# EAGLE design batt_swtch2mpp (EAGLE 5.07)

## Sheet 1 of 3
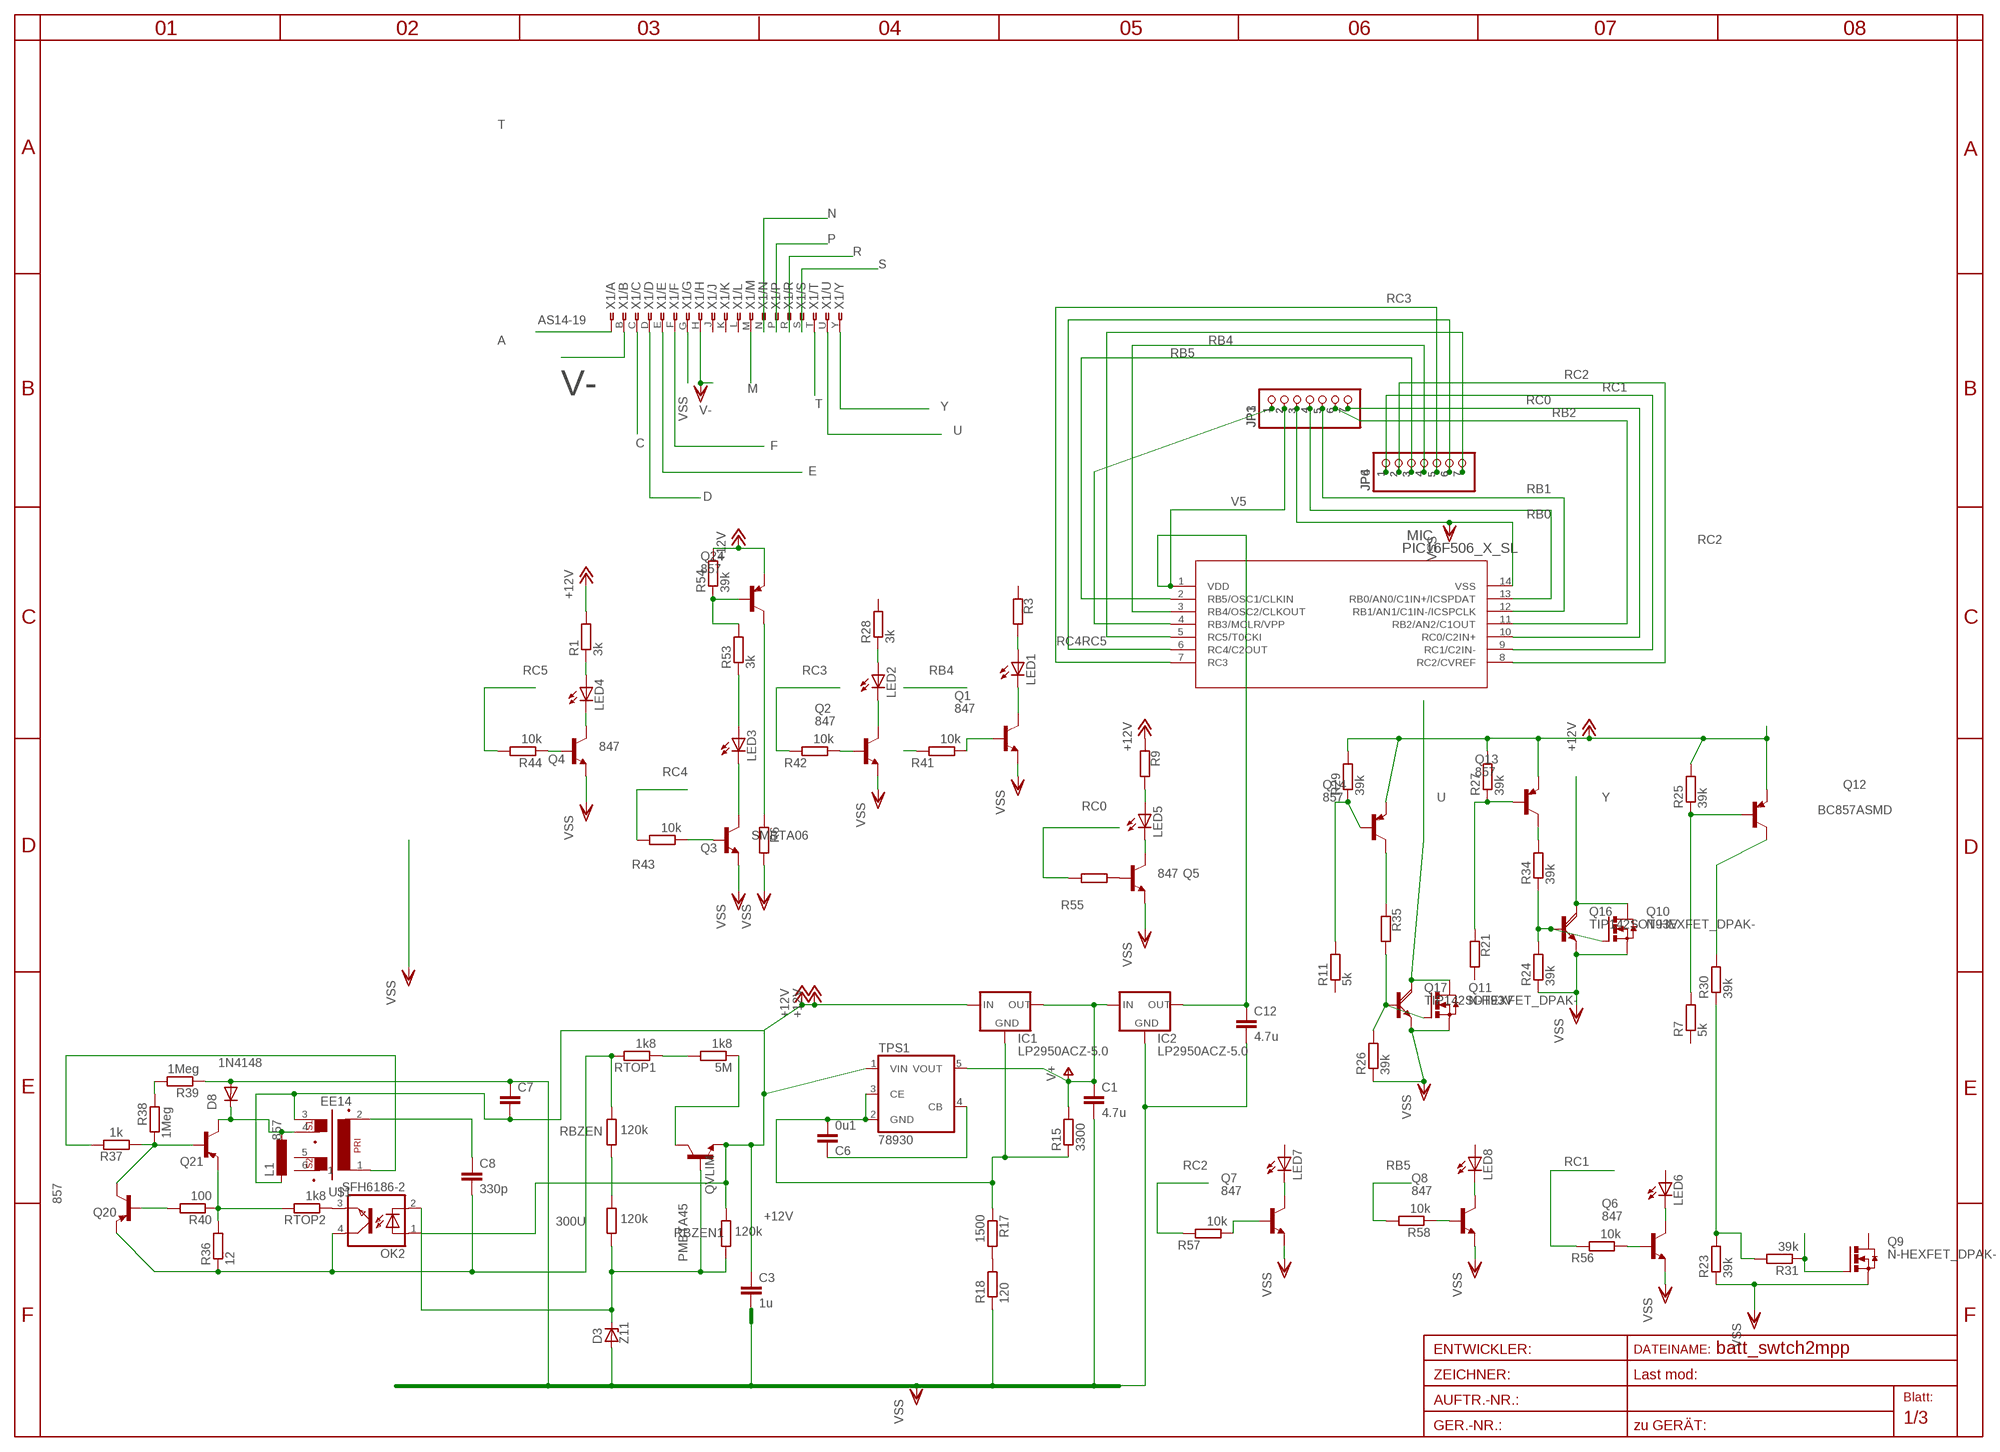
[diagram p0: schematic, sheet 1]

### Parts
5M  1k8  R-EU_R1206  [R1206]
300U  120k  R-EU_R1206  [R1206]
C1  4.7u  C-EUC1206  [C1206]
C3  1u  C-EUC1206  [C1206]
C6  0u1  C-EUC0805  [C0805]
C7  C-EU025-025X050  [C025-025X050]
C8  330p  C-EUC0805  [C0805]
C12  4.7u  C-EUC1206  [C1206]
D3  Z11  ZENER-DIODESOD80C  [SOD80C]
D8  1N4148  DIODE-SMA-DO214  [SMA-DO214AC]
IC1  LP2950ACZ-5.0  [TO92]
IC2  LP2950ACZ-5.0  [TO92]
JP1  PINHD-1X7  [1X07]
JP3  PINHD-1X7  [1X07]
JP4  PINHD-1X7  [1X07]
JP6  PINHD-1X7  [1X07]
L1  L-EU0204/5  [0204/5]
LED1  LEDCHIPLED_1206  [CHIPLED_1206]
LED2  LEDCHIPLED_1206  [CHIPLED_1206]
LED3  LEDCHIPLED_1206  [CHIPLED_1206]
LED4  LEDCHIPLED_1206  [CHIPLED_1206]
LED5  LEDCHIPLED_1206  [CHIPLED_1206]
LED6  LEDCHIPLED_1206  [CHIPLED_1206]
LED7  LEDCHIPLED_1206  [CHIPLED_1206]
LED8  LEDCHIPLED_1206  [CHIPLED_1206]
MIC  PIC16F506_X_SL  [SOIC14_N_MC]
OK2  SFH6186-2  [SMD4]
Q1  847  BC847ASMD  [SOT23]
Q2  847  BC847ASMD  [SOT23]
Q3  SMBTA06  BC847ASMD  [SOT23]
Q4  847  BC847ASMD  [SOT23]
Q5  847  BC847ASMD  [SOT23]
Q6  847  BC847ASMD  [SOT23]
Q7  847  BC847ASMD  [SOT23]
Q8  847  BC847ASMD  [SOT23]
Q9  N-HEXFET_DPAK-  [TO252]
Q10  N-HEXFET_DPAK-  [TO252]
Q11  N-HEXFET_DPAK-  [TO252]
Q12  BC857ASMD  [SOT23-BEC]
Q13  857  BC857ASMD  [SOT23-BEC]
Q14  857  BC857ASMD  [SOT23-BEC]
Q16  TIP142SOT93V  [SOT93V]
Q17  TIP142SOT93V  [SOT93V]
Q20  857  BC857ASMD  [SOT23-BEC]
Q21  857  BC857ASMD  [SOT23-BEC]
Q24  857  BC857ASMD  [SOT23-BEC]
QVLIM  PMBTA45  BC847ALT1SMD  [SOT23]
R1  3k  R-EU_R0805  [R0805]
R3  39k  R-EU_R0805  [R0805]
R6  39k  R-EU_R0805  [R0805]
R7  5k  R-EU_R0805  [R0805]
R9  5k  R-EU_R0805  [R0805]
R11  5k  R-EU_R0805  [R0805]
R15  3300  R-EU_R0805  [R0805]
R17  1500  R-EU_R0805  [R0805]
R18  120  R-EU_R0805  [R0805]
R21  5k  R-EU_R0805  [R0805]
R23  39k  R-EU_R0805  [R0805]
R24  39k  R-EU_R0805  [R0805]
R25  39k  R-EU_R0805  [R0805]
R26  39k  R-EU_R0805  [R0805]
R27  39k  R-EU_R0805  [R0805]
R28  3k  R-EU_R0805  [R0805]
R29  39k  R-EU_R0805  [R0805]
R30  39k  R-EU_R0805  [R0805]
R31  39k  R-EU_R0805  [R0805]
R34  39k  R-EU_R0805  [R0805]
R35  39k  R-EU_R0805  [R0805]
R36  12  R-EU_R0805  [R0805]
R37  1k  R-EU_R0805  [R0805]
R38  1Meg  R-EU_R1206  [R1206]
R39  1Meg  R-EU_R1206  [R1206]
R40  100  R-EU_R0805  [R0805]
R41  10k  R-EU_R0805  [R0805]
R42  10k  R-EU_R0805  [R0805]
R43  10k  R-EU_R0805  [R0805]
R44  10k  R-EU_R0805  [R0805]
R53  3k  R-EU_R0805  [R0805]
R54  39k  R-EU_R0805  [R0805]
R55  10k  R-EU_R0805  [R0805]
R56  10k  R-EU_R0805  [R0805]
R57  10k  R-EU_R0805  [R0805]
R58  10k  R-EU_R0805  [R0805]
RBZEN  120k  R-EU_R1206  [R1206]
RBZEN1  120k  R-EU_R0805  [R0805]
RTOP1  1k8  R-EU_R1206  [R1206]
RTOP2  1k8  R-EU_R1206  [R1206]
TPS1  78930  TPS78930SOT23-5  [SOT25]
U$1  EE14  [EE14]
X1  AS14-19  AS14-19OLIVE  [Y28M-19TK]

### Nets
+12V: C3.1 C7.2 IC1.3(IN) L1.2 OK2.1(A) Q12.E Q13.E Q14.E Q24.E QVLIM.2(E) R1.2 R9.2 R25.2 R27.2 R29.2 R54.2 RBZEN1.1 TPS1.1(VIN) U$1.3
A: X1.A ; also sheet 2,3
B1C2: Q20.C Q21.B R37.1 R38.1
BOOST_EN: Q24.C R6.2 ; also sheet 3
C: X1.C ; also sheet 3
C1: D8.K(C) L1.1 Q21.C U$1.4
CB: 300U.2 D3.C OK2.2(C) QVLIM.1(B) RBZEN1.2
D: X1.D
E: X1.E
EB: Q21.E R36.2 R40.1 RTOP2.2
F: X1.F
G: C8.2 OK2.4(COL) Q20.E R36.1 RBZEN.1 RTOP1.2 X1.G ; also sheet 2,3
GND1: C6.1 TPS1.4(CB)
M: X1.M
N: X1.N
N$1: 300U.1 RBZEN.2
N$3: OK2.3(EMIT) RTOP2.1
N$4: Q8.1(B) R58.1
N$6: Q3.1(B) R43.1
N$7: LED6.C Q6.3(C)
N$8: R17.2 R18.2
N$9: R41.2
N$10: LED8.C Q8.3(C)
N$11: Q2.1(B) R42.1
N$12: Q1.1(B) R41.1
N$14: Q5.1(B) R55.1
N$16: 5M.1 QVLIM.3(C)
N$17: LED7.C Q7.3(C)
N$19: LED1.C Q1.3(C)
N$20: LED1.A R3.1
N$21: Q14.B R11.2 R29.1
N$22: LED2.C Q2.3(C)
N$25: LED2.A R28.1
N$28: Q6.1(B) R56.1
N$29: 5M.2 RTOP1.1
N$30: Q4.1(B) R44.1
N$31: Q7.1(B) R57.1
N$32: LED3.C Q3.3(C)
N$33: LED4.C Q4.3(C)
N$36: LED4.A R1.1
N$37: Q12.C R30.2
N$47: LED5.A R9.1
N$49: Q14.C R35.2
N$50: R23.2 R30.1 R31.2
N$51: Q10.1(G) Q16.B R24.2 R34.1
N$52: LED5.C Q5.3(C)
N$53: Q12.B R7.2 R25.1
N$54: Q9.1(G) R31.1
N$55: Q13.B R21.2 R27.1
N$57: Q13.C R34.2
N$59: Q11.1(G) Q17.B R26.2 R35.1
N$60: R37.2 U$1.1
N$61: C8.1 U$1.2
N$62: R38.2 R39.2
N$63: Q20.B R40.2
N$81: Q24.B R53.2 R54.1
N$82: LED3.A R53.1
P: X1.P
R: X1.R
RB0: JP1.4 JP3.4 MIC.13(RB0/AN0/C1IN+/ICSPDAT) ; also sheet 2
RB1: JP1.5 JP3.5 MIC.12(RB1/AN1/C1IN-/ICSPCLK) ; also sheet 2
RB2: JP1.6 JP3.6 MIC.11(RB2/AN2/C1OUT) ; also sheet 2
RB4: JP4.4 JP6.4 MIC.3(RB4/OSC2/CLKOUT)
RB5: JP4.3 JP6.3 MIC.2(RB5/OSC1/CLKIN) R58.2
RC0: JP1.7 JP3.7 MIC.10(RC0/C2IN+) R55.2
RC1: JP4.1 JP6.1 MIC.9(RC1/C2IN-) R56.2
RC2: JP4.2 JP6.2 MIC.8(RC2/CVREF) R57.2
RC3: JP4.5 JP6.5 MIC.7(RC3) R42.2
RC4: JP4.6 JP6.6 MIC.6(RC4/C2OUT) R43.2
RC5: JP4.7 JP6.7 MIC.5(RC5/T0CKI) R44.2
S: X1.S ; also sheet 2
T: X1.T ; also sheet 2
U: Q11.3(D) Q17.C X1.U
V5: C12.1 IC2.1(OUT) JP1.2 JP3.2 MIC.1(VDD) ; also sheet 2
V+: C1.1 IC1.1(OUT) IC2.3(IN) R15.2 TPS1.5(VOUT) ; also sheet 3
V-: C1.2 C3.2 C6.2 C7.1 C12.2 D3.A D8.A IC1.2(GND) IC2.2(GND) JP1.3 JP3.3 MIC.14(VSS) Q1.2(E) Q2.2(E) Q3.2(E) Q4.2(E) Q5.2(E) Q6.2(E) Q7.2(E) Q8.2(E) Q9.2(S) Q10.2(S) Q11.2(S) Q16.E Q17.E R6.1 R15.1 R17.1 R18.1 R23.1 R24.1 R26.1 R39.1 TPS1.2(GND) TPS1.3(CE) X1.B X1.H ; supply symbol labelled VSS ; also sheet 2,3
WIND: JP1.1 JP3.1 MIC.4(RB3/MCLR/VPP)
Y: Q10.3(D) Q16.C X1.Y
Unconnected: LED6.A LED7.A LED8.A Q9.3(D) R3.2 R7.1 R11.1 R21.1 R28.2 U$1.5 U$1.6 X1.J X1.K X1.L

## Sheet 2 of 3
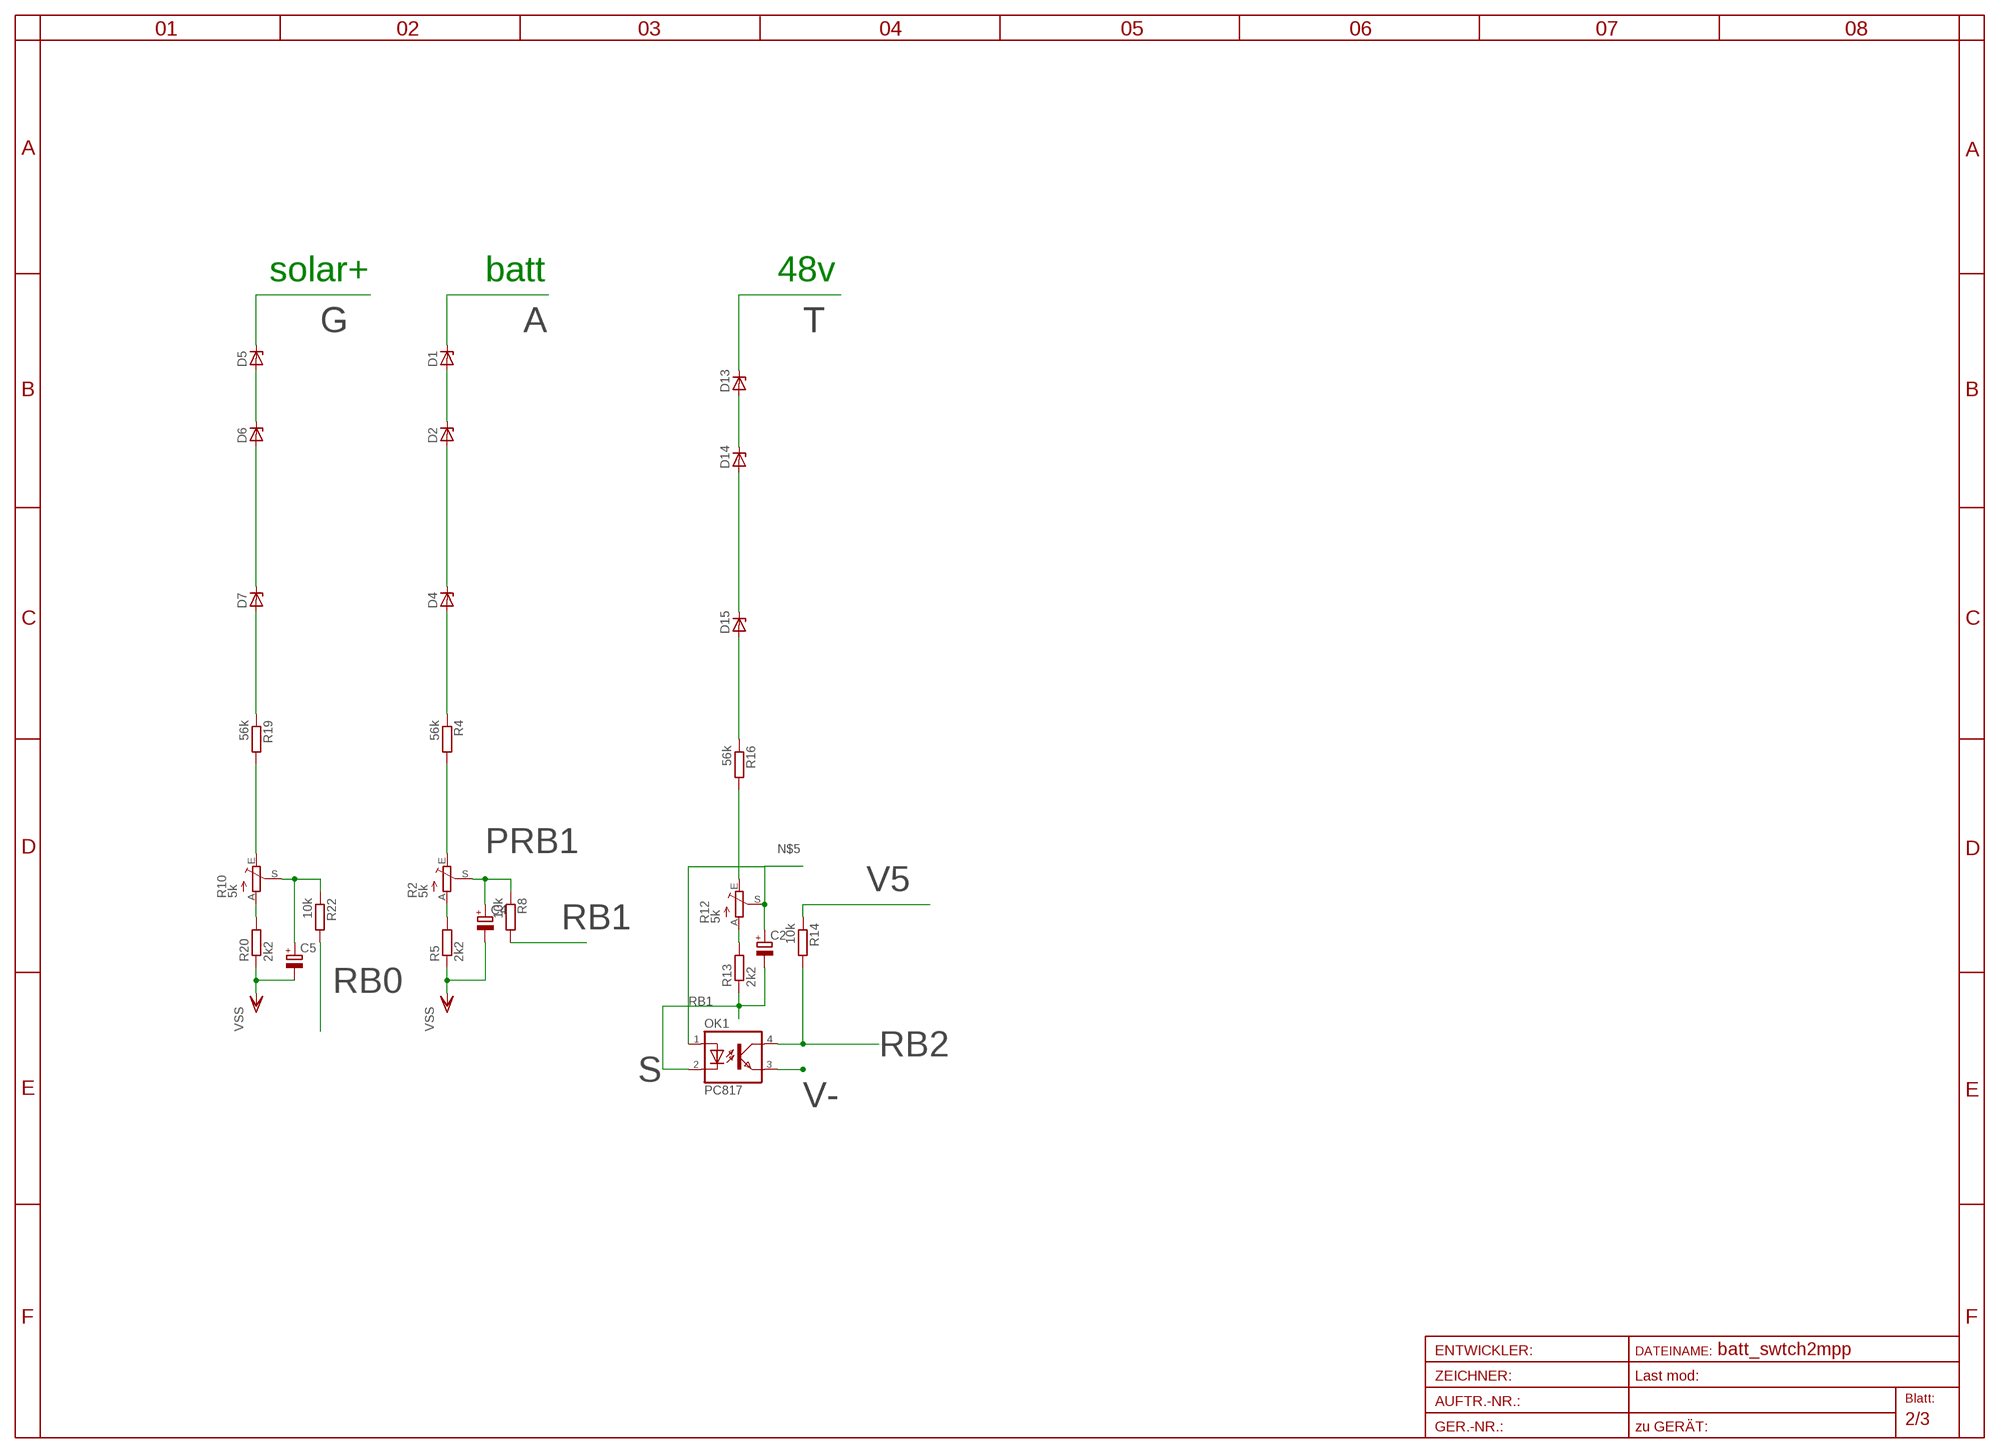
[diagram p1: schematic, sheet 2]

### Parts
C2  CPOL-EUE2,5-6E  [E2,5-6E]
C4  CPOL-EUE2,5-6E  [E2,5-6E]
C5  CPOL-EUE2,5-6E  [E2,5-6E]
D1  ZENER-DIODESOD80C  [SOD80C]
D2  ZENER-DIODESOD80C  [SOD80C]
D4  ZENER-DIODESOD80C  [SOD80C]
D5  ZENER-DIODESOD80C  [SOD80C]
D6  ZENER-DIODESOD80C  [SOD80C]
D7  ZENER-DIODESOD80C  [SOD80C]
D13  ZENER-DIODESOD80C  [SOD80C]
D14  ZENER-DIODESOD80C  [SOD80C]
D15  ZENER-DIODESOD80C  [SOD80C]
OK1  PC817  [DIL04]
R2  5k  TRIM_EU-S64W  [S64W]
R4  56k  R-EU_R0805  [R0805]
R5  2k2  R-EU_R0805  [R0805]
R8  10k  R-EU_R0805  [R0805]
R10  5k  TRIM_EU-S64W  [S64W]
R12  5k  TRIM_EU-S64W  [S64W]
R13  2k2  R-EU_R0805  [R0805]
R14  10k  R-EU_R0805  [R0805]
R16  56k  R-EU_R0805  [R0805]
R19  56k  R-EU_R0805  [R0805]
R20  2k2  R-EU_R0805  [R0805]
R22  10k  R-EU_R0805  [R0805]

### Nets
A: D1.C ; also sheet 1,3
G: D5.C ; also sheet 1,3
N$5: C2.+ OK1.1(A) R12.S
N$18: D15.A R16.1
N$23: D14.A D15.C
N$24: D13.A D14.C
N$26: R12.A R13.2
N$34: D7.A R19.1
N$35: D6.A D7.C
N$38: D5.A D6.C
N$39: R10.E R19.2
N$40: R10.A R20.2
N$41: D4.A R4.1
N$42: D2.A D4.C
N$43: D1.A D2.C
N$44: R2.E R4.2
N$45: R2.A R5.2
N$48: C5.+ R10.S R22.1
N$65: R12.E R16.2
PRB1: C4.+ R2.S R8.1 ; also sheet 3
RB0: R22.2 ; also sheet 1
RB1: R8.2 ; also sheet 1
RB2: OK1.4(COL) R14.2 ; also sheet 1
S: C2.- OK1.2(C) R13.1 ; also sheet 1
T: D13.C ; also sheet 1
V5: R14.1 ; also sheet 1
V-: C4.- C5.- OK1.3(EMIT) R5.1 R20.1 ; supply symbol labelled VSS ; also sheet 1,3

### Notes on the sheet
- solar+ | batt | 48v

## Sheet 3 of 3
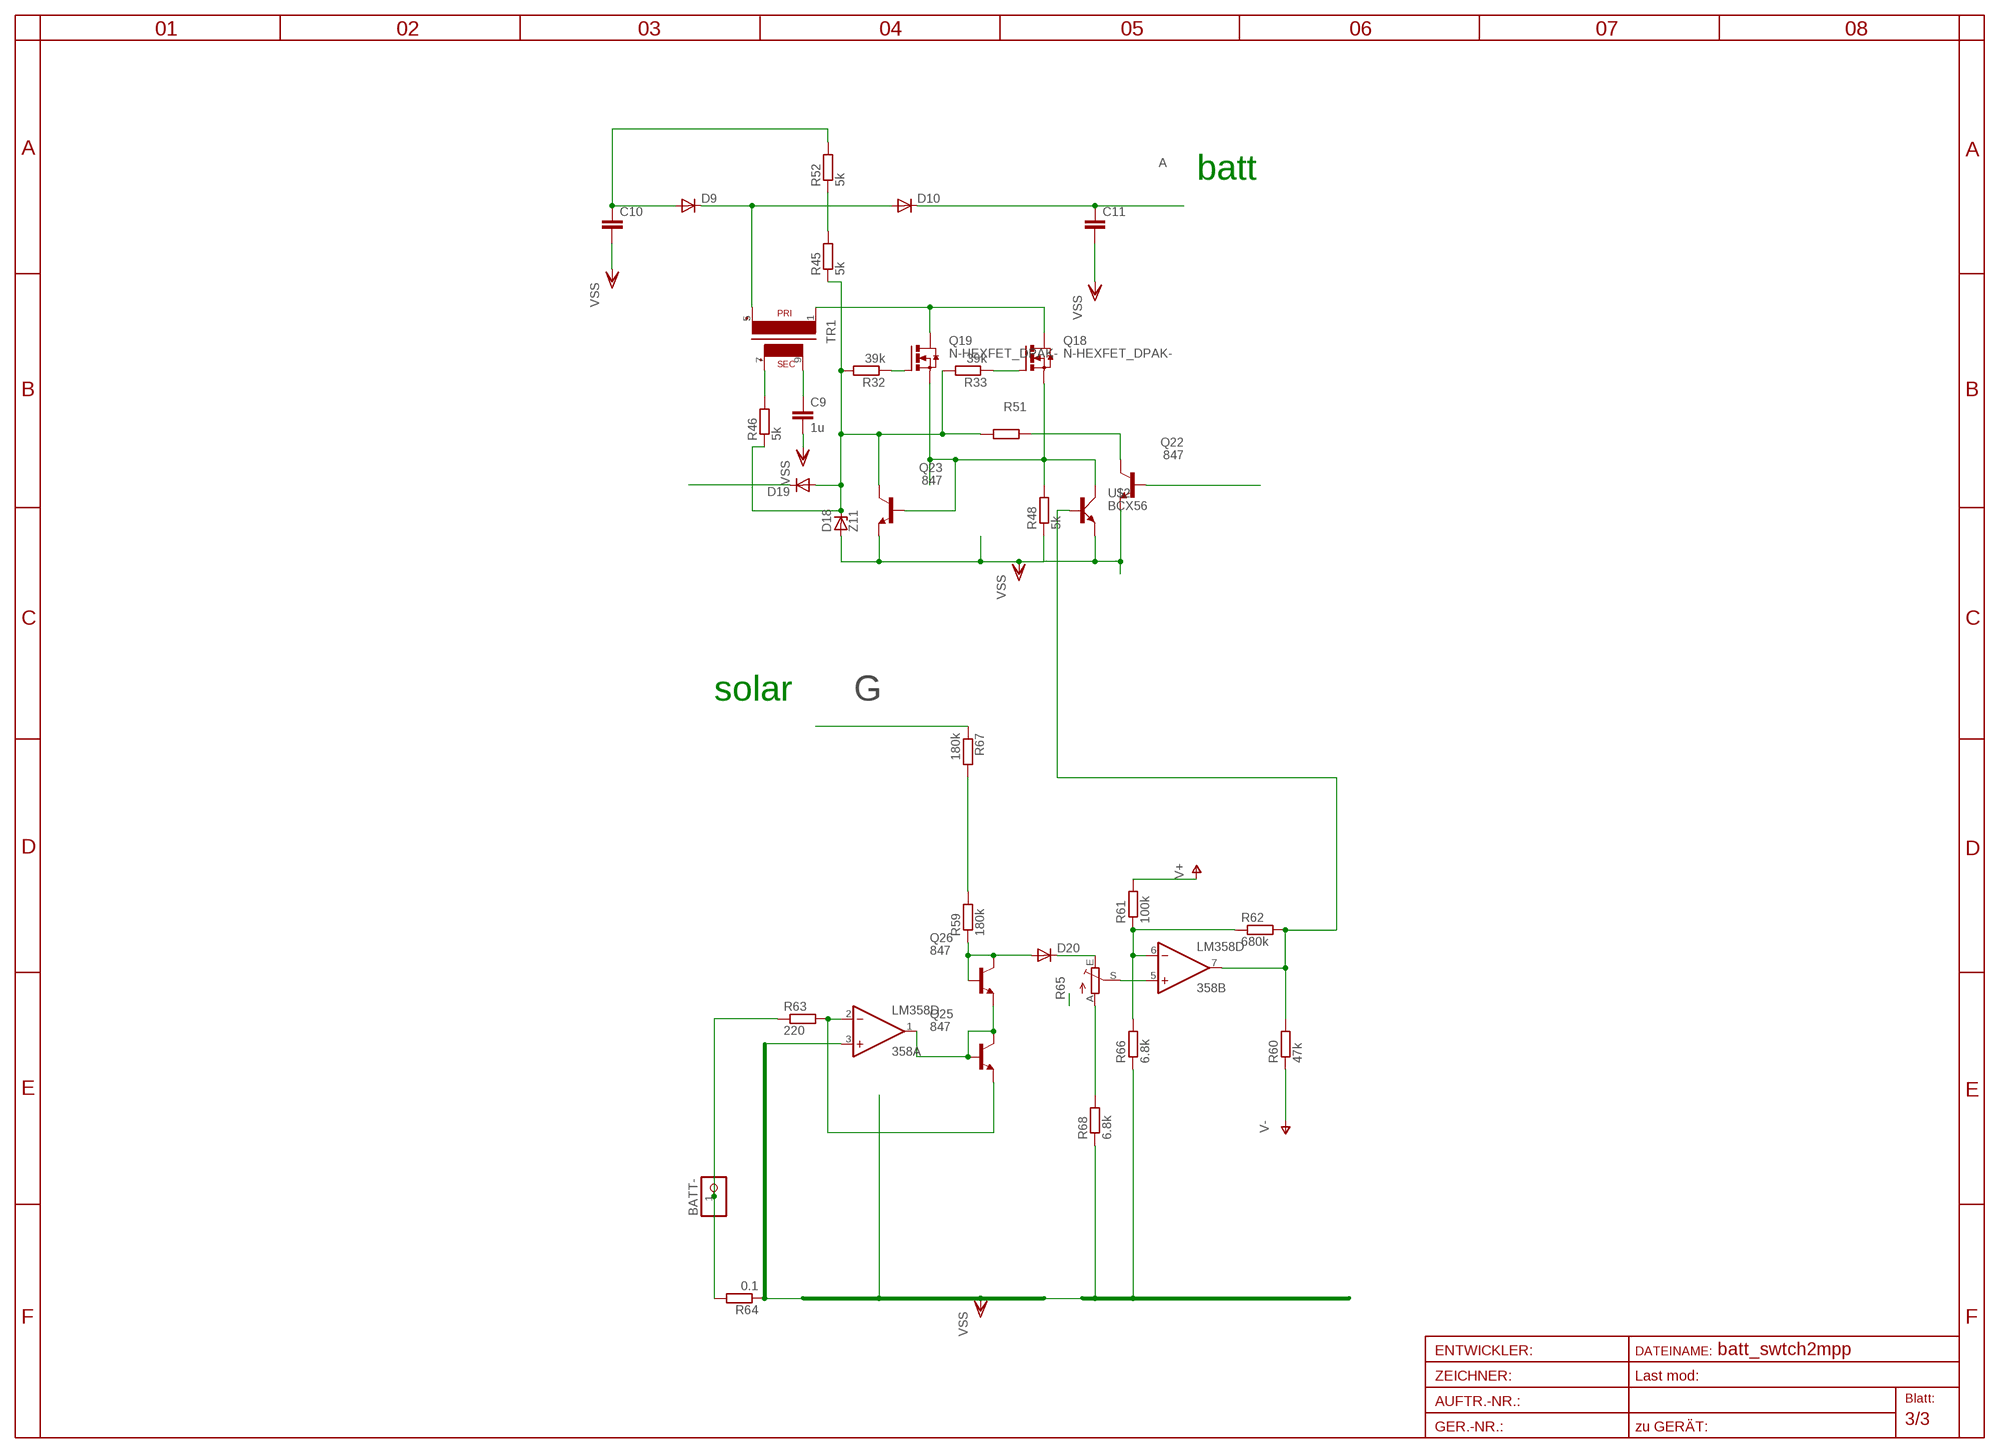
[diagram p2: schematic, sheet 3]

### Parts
358  LM358D  [SO08]
BATT-  PINHD-1X1  [1X01]
C9  1u  C-EUC1206  [C1206]
C10  C-EU075-052X106  [C075-052X106]
C11  C-EU075-052X106  [C075-052X106]
D9  DIODE-SMC  [SMC]
D10  DIODE-SMC  [SMC]
D18  Z11  ZENER-DIODESOD80C  [SOD80C]
D19  DIODE-MINIMELF  [MINIMELF]
D20  DIODE-SOD80C  [SOD80C]
Q18  N-HEXFET_DPAK-  [TO252]
Q19  N-HEXFET_DPAK-  [TO252]
Q22  847  BC847ASMD  [SOT23]
Q23  847  BC847ASMD  [SOT23]
Q25  847  BC847ALT1SMD  [SOT23]
Q26  847  BC847ALT1SMD  [SOT23]
R32  39k  R-EU_R0805  [R0805]
R33  39k  R-EU_R0805  [R0805]
R45  5k  R-EU_R1206  [R1206]
R46  5k  R-EU_R0805  [R0805]
R48  5k  R-EU_R2010  [R2010]
R51  39k  R-EU_R0805  [R0805]
R52  5k  R-EU_R1206  [R1206]
R59  180k  R-EU_R1206  [R1206]
R60  47k  R-EU_R1206  [R1206]
R61  100k  R-EU_R0805  [R0805]
R62  680k  R-EU_R1206  [R1206]
R63  220  R-EU_R0805  [R0805]
R64  0.1  R-EU_R2512  [R2512]
R65  TRIM_EU-S64W  [S64W]
R66  6.8k  R-EU_R1206  [R1206]
R67  180k  R-EU_R1206  [R1206]
R68  6.8k  R-EU_R0805  [R0805]
TR1  VR11  [1X3WDIRVER]
U$2  BCX56  [SOT223]

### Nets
A: C11.1 D10.C ; also sheet 1,2
BOOST_EN: D19.C ; also sheet 1
C: BATT-.1 R63.1 R64.2 ; also sheet 1
DQ18: Q18.3(D) Q19.3(D) TR1.1
G: C10.1 D9.A R52.2 R67.1 ; also sheet 1,2
GQ18: Q18.2(S) Q19.2(S) Q23.1(B) R48.2 U$2.2(C)
N$27: D18.C D19.A Q23.3(C) R32.2 R33.2 R45.1 R46.1 R51.1
N$56: Q18.1(G) R33.1
N$58: Q19.1(G) R32.1
N$64: R46.2 TR1.7(S3)
N$66: 358.2(A:-IN) Q25.2(E) R63.2
N$67: 358.1(A:OUT) Q25.1(B) Q25.3(C) Q26.2(E)
N$71: Q22.3(C) R51.2
N$74: C9.1 TR1.9(S4)
N$75: D20.A Q26.1(B) Q26.3(C) R59.1
N$80: R45.2 R52.1
N$85: D20.C R65.E
N$86: 358.5(B:+IN) R65.S
N$87: 358.6(B:-IN) R61.1 R62.1 R66.2
N$88: R59.2 R67.2
N$89: 358.7(B:OUT) R60.2 R62.2 U$2.1(B)
N$90: R65.A R68.2
NODOTL2: D9.C D10.A TR1.5(P2)
PRB1: Q22.1(B) ; also sheet 2
V+: R61.2 ; also sheet 1
V-: 358.3(A:+IN) C9.2 C10.2 C11.2 D18.A Q22.2(E) Q23.2(E) R48.1 R60.1 R64.1 R66.1 R68.1 U$2.3(E) ; supply symbol labelled VSS ; also sheet 1,2

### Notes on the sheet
- batt
- solar

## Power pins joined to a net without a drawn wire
V+: 358.8(P:V+)
V-: 358.4(P:V-)

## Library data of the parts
5M 300U R4 R5 R8 R13-R20 R22 R36-R40 R59-R64 R66-R68 RBZEN RBZEN1 RTOP1 RTOP2 = rcl:R-EU_: RESISTOR, European symbol
358 = linear:LM358: OP AMP also LM158; LM258; LM2904 Source: http://cache.national.com/ds/LM/LM158.pdf
BATT- = pinhead:PINHD-1X1: PIN HEADER
C1 C3 C6-C12 = rcl:C-EU: CAPACITOR, European symbol
C2 C4 C5 = rcl:CPOL-EU: POLARIZED CAPACITOR, European symbol
D1-D7 D13-D15 D18 = diode:ZENER-DIODE: Z-Diode
D8-D10 D19 D20 = diode:DIODE-: DIODE
IC1 IC2 = v-reg:LP2950?*: Source: http://cache.national.com/ds/LP/LP2950.pdf
JP1 JP3 JP4 JP6 = pinhead:PINHD-1X7: PIN HEADER
L1 = rcl:L-EU: INDUCTOR, European symbol
LED1-LED8 = led:LED: LED
MIC = pic16f506mc:PIC16F506_X_SL
OK1 = optocoupler:PC817: SHARP OPTO COUPLER
OK2 = optocoupler:SFH618?*: Optocoupler, Phototransistor Output, Low Input Current Source: http://www.vishay.com/docs/83673/sfh618.pdf
Q1-Q8 Q22 Q23 Q25 Q26 QVLIM = transistor-npn:BC847*: NPN Transistor
Q9-Q11 Q18 Q19 = transistor-power:N-HEXFET_?-*: HEXFET® Power MOSFET
Q12-Q14 Q20 Q21 Q24 = transistor-pnp:BC857*: PNP Transistror
Q16 Q17 = transistor-power:TIP142: NPN DARLINGTON TRANSISTOR
R1 R3 R6 R7 R9 R11 R21 R23-R35 R41-R46 R48 R51-R58 = rcl-2:R-EU_: RESISTOR, European symbol
R2 R10 R12 R65 = pot:TRIM_EU-: POTENTIOMETER
TPS1 = v-reg:TPS78930
TR1 = trafo:VR11: TRANSFORMER 1 primary winding, 1 secondary winding BLOCK
U$1 = trafo:EE14
U$2 = transistor-power:BCX56
X1 = con-deutsch:AS14-19: DEUTSCH Connector

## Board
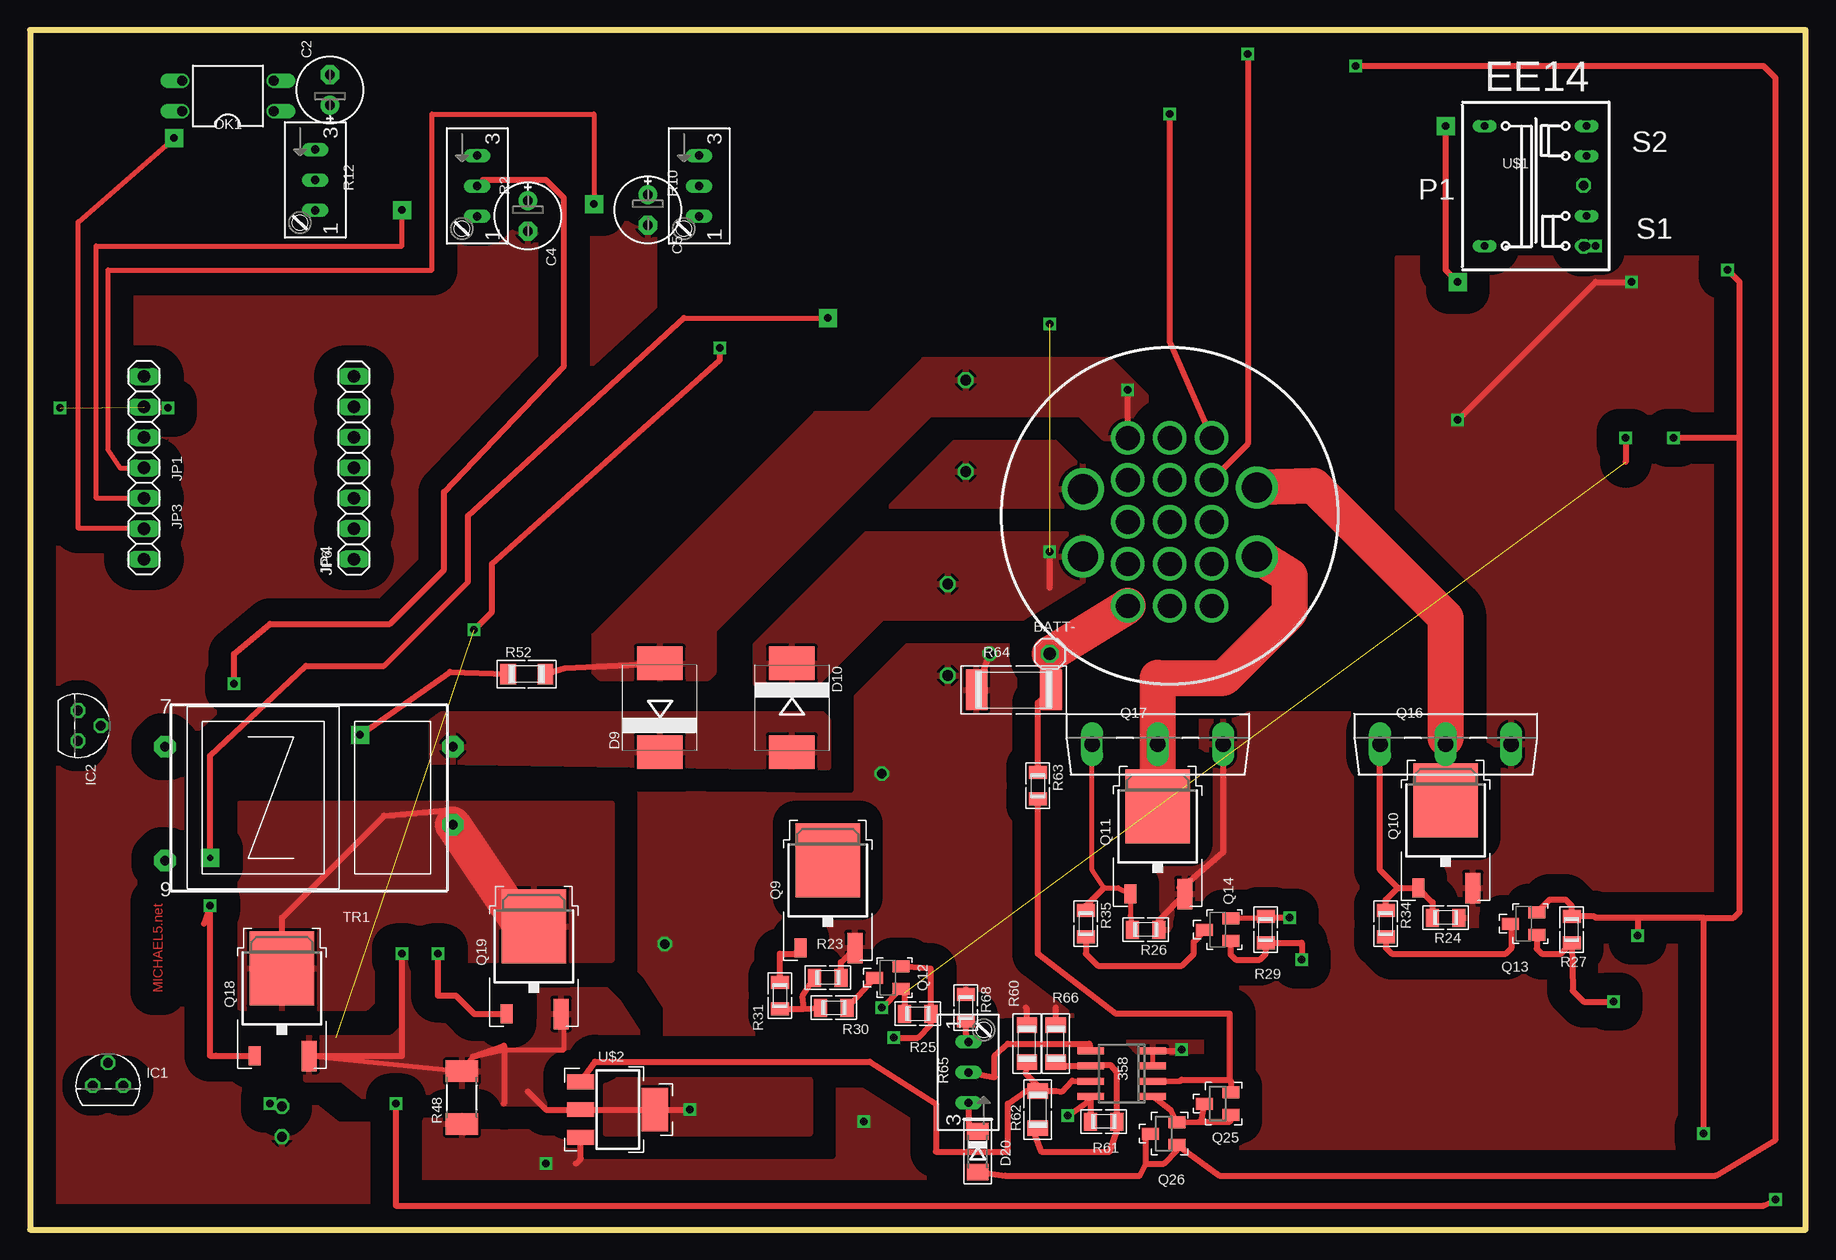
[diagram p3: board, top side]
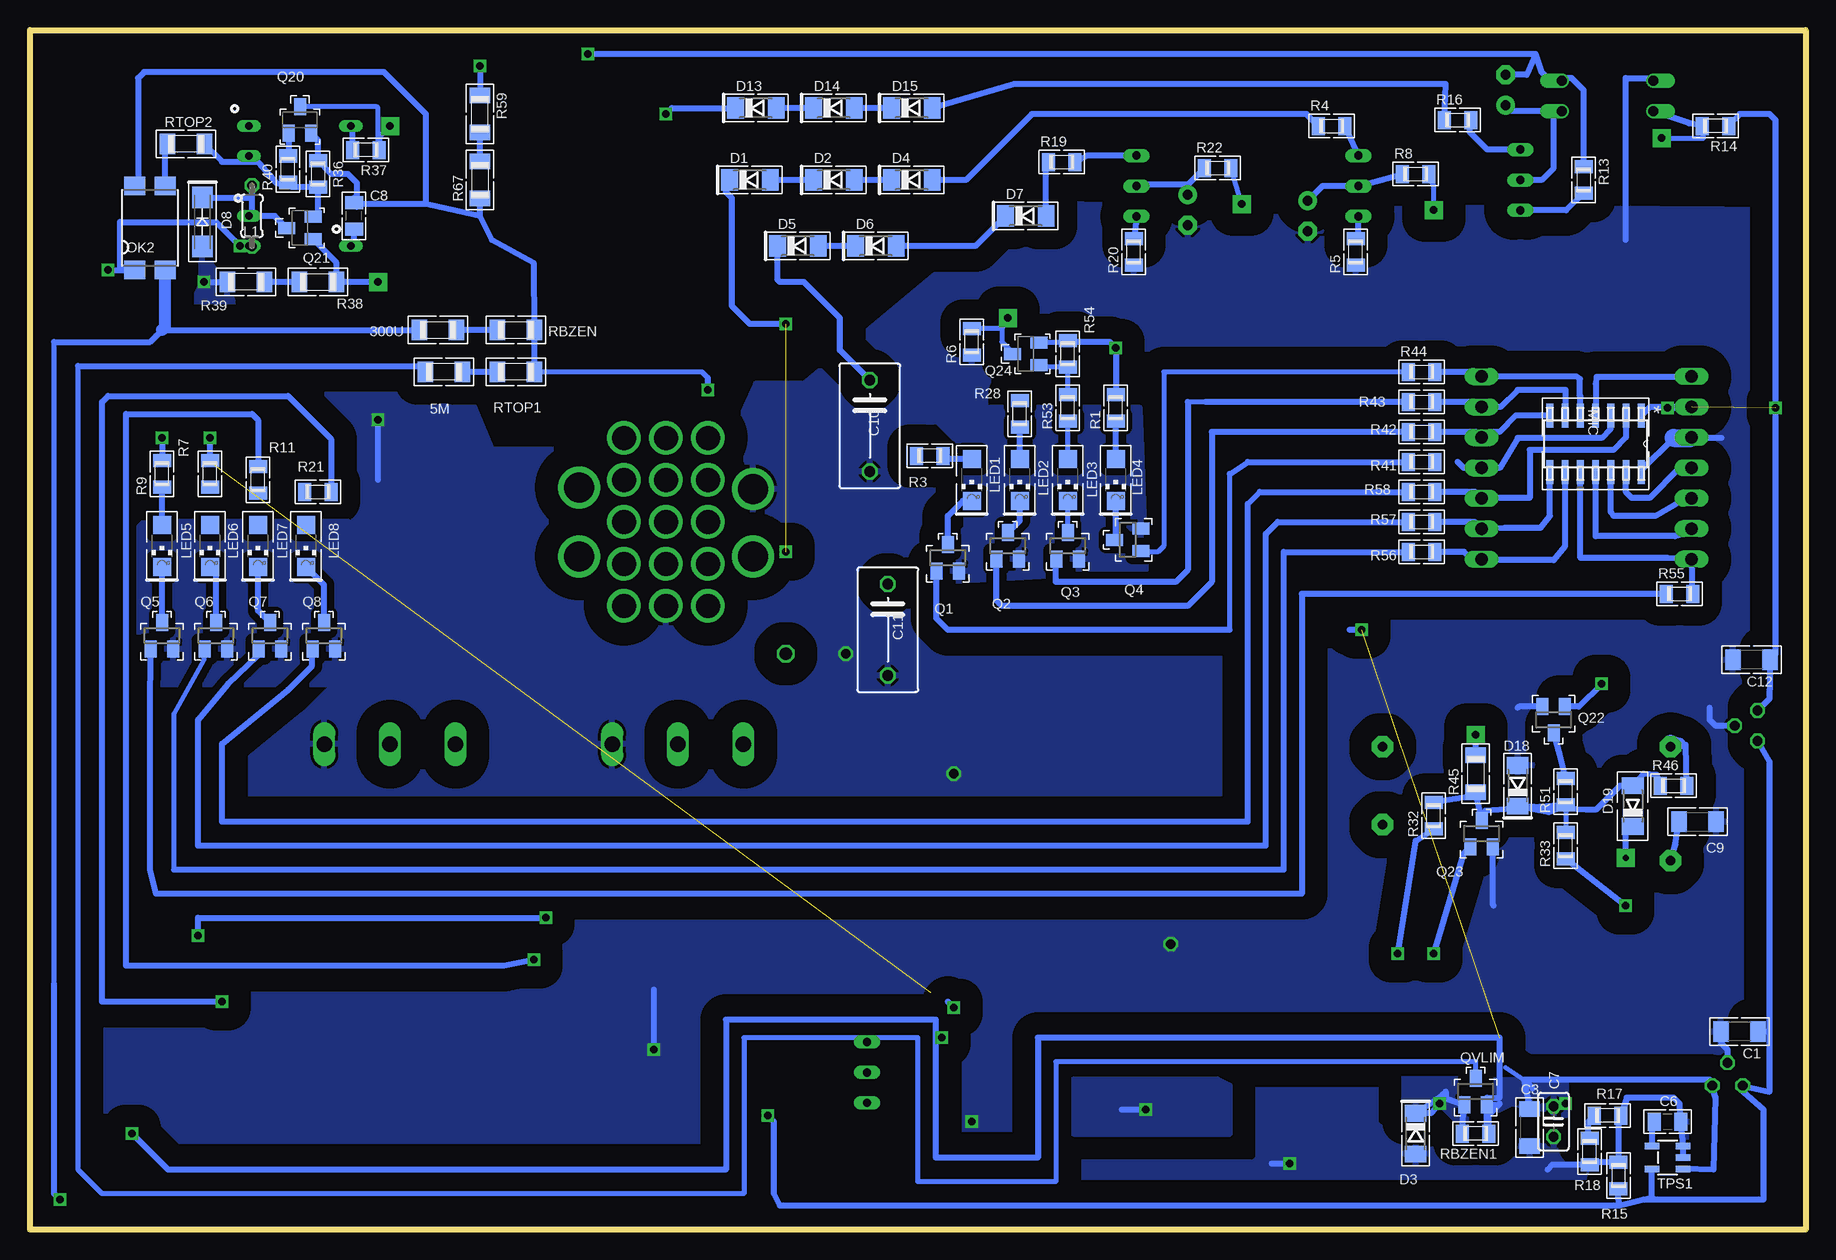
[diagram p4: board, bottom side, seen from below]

Size 148 x 100 mm. Coordinates in mm from the lower left corner, seen from the top.
Outline: 148,0 148,100 0,100 0,0 148,0
Copper layers (1*16): Top 0.035mm / dielectric 1.5mm / Bottom 0.035mm
Design rules "default *": minimum track width 40mil, minimum drill 30mil, track to track 8mil, track to pad 8mil, pad to pad 8mil, via to via 8mil, smd to smd 8mil, copper to edge 40mil, drill to drill 8mil, minimum pad ring 8mil, minimum via ring 8mil, stop-mask expansion 4mil, vias tented up to drill 0mil, thermal gap 10mil

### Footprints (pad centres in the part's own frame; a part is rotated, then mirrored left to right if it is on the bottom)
R1206 = smd 1.3 x 1.7: 1 -1.55,0; 2 1.55,0
SO08 = smd 0.6 x 2.2: 1 -1.905,-2.6; 2 -0.635,-2.6; 3 0.635,-2.6; 4 1.905,-2.6; 5 1.905,2.6; 6 0.635,2.6; 7 -0.635,2.6; 8 -1.905,2.6
1X01 = drill 1.016 octagon: 1 0,0
C1206 = smd 1.3 x 1.7: 1 -1.55,0; 2 1.55,0
E2,5-6E = drill 0.813 pad 1.575 round: + -1.27,0 | drill 0.813 pad 1.575 octagon: - 1.27,0
C0805 = smd 1.1 x 1.5: 1 -1.1,0; 2 1.1,0
C025-025X050 = drill 0.813 octagon: 1 -1.27,0; 2 1.27,0
C075-052X106 = drill 0.914 octagon: 1 -3.81,0; 2 3.81,0
SOD80C = smd 1.4 x 1.8: A 1.7,0; C -1.7,0
SMA-DO214AC = smd 1.8 x 1.7: A 2.05,-0.127; K -2.05,-0.127
SMC = smd 2.8 x 3.8: A 3.7,0; C -3.7,0
MINIMELF = smd 1.4 x 1.8: A 1.7,0; C -1.7,0
TO92 = drill 0.813 octagon: 1 -1.27,0; 2 0,1.905; 3 1.27,0
1X07 = drill 1.016 long: 1 -7.62,0; 2 -5.08,0; 3 -2.54,0; 4 0,0; 5 2.54,0; 6 5.08,0; 7 7.62,0
0204/5 = drill 0.813 octagon: 1 -2.54,0; 2 2.54,0
CHIPLED_1206 = smd 1.5 x 1.5: A 0,-1.75; C 0,1.75
SOIC14_N_MC = smd 1.981 x 0.559: 1 -2.362,3.81; 2 -2.362,2.54; 3 -2.362,1.27; 4 -2.362,0; 5 -2.362,-1.27; 6 -2.362,-2.54; 7 -2.362,-3.81; 8 2.362,-3.81; 9 2.362,-2.54; 10 2.362,-1.27; 11 2.362,0; 12 2.362,1.27; 13 2.362,2.54; 14 2.362,3.81
DIL04 = drill 0.813 offset: 1 -1.27,-3.81; 2 1.27,-3.81; 3 1.27,3.81; 4 -1.27,3.81
SMD4 = smd 1.78 x 1.55: 1 -1.27,-3.5; 2 1.27,-3.5; 3 1.27,3.5; 4 -1.27,3.5
SOT23 = smd 1 x 1.4: 1 -0.95,-1.1; 2 0.95,-1.1; 3 0,1.1
TO252 = smd 1 x 1.6: 1 -2.28,-3.53 | smd 1.27 x 2.54: 2 2.28,-3.53 | smd 5.4 x 6.2: 3 0,3.77
SOT23-BEC = smd 1 x 1.4: B -0.95,-1.1; C 0,1.1; E 0.95,-1.1
SOT93V = drill 1.3 pad 1.676 long: B -5.461,-2.54; C 0,-2.54; E 5.461,-2.54
R0805 = smd 1.1 x 1.5: 1 -1.1,0; 2 1.1,0
S64W = drill 0.7 long: A 2.54,1.27; E -2.54,1.27; S 0,1.27
R2010 = smd 1.8 x 2.7: 1 -2.2,0; 2 2.2,0
R2512 = smd 1.8 x 3.4: 1 -3.1,0; 2 3.1,0
SOT25 = smd 0.55 x 1.2: 1 -0.95,-1.3; 2 0,-1.3; 3 0.95,-1.3; 4 0.95,1.3; 5 -0.95,1.3
1X3WDIRVER = drill 0.8 pad 1.778 octagon: 1 -12,2.25; 5 -12,-4.25; 7 12,-4.25; 9 12,5.25
EE14 = drill 0.6 pad 1 long: 1 4.25,-5; 2 4.25,5; 3 -4.25,5 | drill 0.6 pad 1.016 long: 4 -4.25,2.5; 5 -4.25,-2.5; 6 -4.25,-5
SOT223 = smd 1.219 x 2.235: 1 -2.311,-3.099; 2 0,-3.099; 3 2.311,-3.099 | smd 3.6 x 2.2: 4 0,3.099
Y28M-19TK = drill 2.5 pad 3.5 round: A -7.25,-2.875; B -7.25,2.75; U 7.25,-2.875; Y 7.25,2.875 | drill 2 pad 2.54 round: C -3.5,-7; D -3.5,-3.5; E -3.5,0; F -3.5,3.5; G -3.5,7; H 0,-7; J 0,-3.5; K 0,0; L 0,3.5; M 0,7; N 3.5,-7; P 3.5,-3.5; R 3.5,0; S 3.5,3.5; T 3.5,7

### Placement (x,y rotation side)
5M  113.5,71.5 0 bottom
300U  114,75 180 bottom
358  91,13 90 top
BATT-  85,48 0 top
C1  5.5,16.5 180 bottom
C2  25,95 90 top
C3  23,8.5 270 bottom
C4  41.5,84.5 270 top
C5  51.5,85 270 top
C6  11.5,9 0 bottom
C7  21,9 90 bottom
C8  121,84.5 90 bottom
C9  9,34 0 bottom
C10  78,67 270 bottom
C11  76.5,50 270 bottom
C12  4.5,47.5 180 bottom
D1  88,87.5 0 bottom
D2  81,87.5 0 bottom
D3  32.5,8 270 bottom
D4  74.5,87.5 0 bottom
D5  84,82 0 bottom
D6  77.5,82 0 bottom
D7  65,84.5 0 bottom
D8  133.5,84 270 bottom
D9  52.5,43.5 90 top
D10  63.5,43.5 270 top
D13  87.5,93.5 0 bottom
D14  81,93.5 0 bottom
D15  74.5,93.5 0 bottom
D18  24,37 90 bottom
D19  14.4,35.3 90 bottom
D20  79,6.5 270 top
IC1  6.5,12 0 top
IC2  4,42 270 top
JP1  9.5,63.5 270 top
JP3  9.5,63.5 270 top
JP4  27,63.5 90 top
JP6  27,63.5 90 top
L1  129.5,84.5 270 bottom
LED1  69.5,62.5 180 bottom
LED2  65.5,62.5 180 bottom
LED3  61.5,62.5 180 bottom
LED4  57.5,62.5 180 bottom
LED5  137,57 180 bottom
LED6  133,57 180 bottom
LED7  129,57 180 bottom
LED8  125,57 180 bottom
MIC  17.5,65.5 270 bottom
OK1  16.5,94.5 90 top
OK2  138,83.5 0 bottom
Q1  71.5,56 0 bottom
Q2  66.5,57 0 bottom
Q3  61.5,57 0 bottom
Q4  56.5,57.5 90 bottom
Q5  137,49.5 0 bottom
Q6  132.5,49.5 0 bottom
Q7  128,49.5 0 bottom
Q8  123.5,49.5 0 bottom
Q9  66.5,27 0 top
Q10  118,32 0 top
Q11  94,31.5 0 top
Q12  71.5,21 90 top
Q13  124.5,25.5 90 top
Q14  99,25 90 top
Q16  118,43 0 top
Q17  94,43 0 top
Q18  21,18 0 top
Q19  42,21.5 0 top
Q20  125.5,92.5 0 bottom
Q21  125.5,83.5 90 bottom
Q22  21,42.5 180 bottom
Q23  27,33 0 bottom
Q24  65,73 90 bottom
Q25  99,10.5 90 top
Q26  94.5,8 90 top
QVLIM  27.5,11.5 0 bottom
R1  57.5,68.5 90 bottom
R2  36,87 270 top
R3  73,64.5 180 bottom
R4  39.5,92 0 bottom
R5  37.5,81.5 90 bottom
R6  69.5,74 90 bottom
R7  133,63 90 bottom
R8  32.5,88 0 bottom
R9  137,63 90 bottom
R10  54.5,87 270 top
R11  129,62.5 90 bottom
R12  22.5,87.5 270 top
R13  18.5,87.5 270 bottom
R14  7.5,92 180 bottom
R15  15.6,4.5 270 bottom
R16  29,92.5 0 bottom
R17  16.5,9.5 180 bottom
R18  18,6.5 90 bottom
R19  62,89 0 bottom
R20  56,81.5 90 bottom
R21  124,61.5 0 bottom
R22  49,88.5 0 bottom
R23  66.5,21 180 top
R24  118,26 180 top
R25  74,18 0 top
R26  93,25 180 top
R27  128.5,25 90 top
R28  65.5,68 90 bottom
R29  103,25 90 top
R30  67,18.5 0 top
R31  62.5,19.5 270 top
R32  31,34.5 90 bottom
R33  20,32 90 bottom
R34  113,25.5 270 top
R35  88,25.5 270 top
R36  124,88 270 bottom
R37  120,90 180 bottom
R38  124,79 180 bottom
R39  130,79 0 bottom
R40  126.5,88.4 90 bottom
R41  32,64 0 bottom
R42  32,66.5 0 bottom
R43  32,69 0 bottom
R44  32,71.5 0 bottom
R45  27.5,38 90 bottom
R46  11,37 0 bottom
R48  36,11 90 top
R51  20,36.5 90 bottom
R52  41.4,46.3 0 top
R53  61.5,68.5 90 bottom
R54  61.5,73 90 bottom
R55  10.5,53 0 bottom
R56  32,56.5 0 bottom
R57  32,59 0 bottom
R58  32,61.5 0 bottom
R59  110.5,93 270 bottom
R60  83.1,15.5 270 top
R61  89.5,9 180 top
R62  84,10 90 top
R63  84,37 270 top
R64  82,45 0 top
R65  79.5,13.1 90 top
R66  85.5,15.5 270 top
R67  110.5,87.5 90 bottom
R68  78,18.5 270 top
RBZEN  107.5,75 180 bottom
RBZEN1  27.5,8 180 bottom
RTOP1  107.5,71.5 0 bottom
RTOP2  135,90.5 0 bottom
TPS1  11.5,6 90 bottom
TR1  23.25,36 180 top
U$1  125.5,87 180 top
U$2  49,10 270 top
X1  95,59 0 top

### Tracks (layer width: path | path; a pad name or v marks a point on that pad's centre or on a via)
+12V  (via drill 0.6)  (1 unrouted)
  Top 0.406: Q14.E 103,25.95 R29.2
  Top 0.5: Q13.E 126.65,27.5 128,27.5 128.5,27 R27.2 130.4,26.1 130.5,26 134,26 | U$1.3 129.54,82 L1.2 | v141.5,80 142.5,79 142.5,66 | 142.5,66 142.5,26.5 142,26 139.5,26 | R29.2 103,26 v105,26 | 134,26 v134,24.5 | v139.5,8 139.5,26 | 139.5,26 134,26 | v72,16 74,16 75.1,17.1 R25.2 75.1,21.75 Q12.E | v57.5,73.5 57.5,72.5 38.5,55.5 38.5,51.5 v37,50 | 142.5,66 v137,66
  Bottom 0.406: 23.5,12.5 25,13.5 | Q24.E 61.65,73.95 R54.2
  Bottom 0.5: 23.5,12.5 C3.1 | 8,12.5 7.5,11 7.65,5 TPS1.1 | QVLIM.2 26.55,8.65 RBZEN1.1 26.4,9.4 26.5,9.5 25.5,10.5 | 23.5,12.5 22.73,11.77 | 8,12.5 23.5,12.5 | QVLIM.2 25.5,10.45 | U$1.3 v130.5,82 132.5,84 140.5,84 140.5,80.27 OK2.1 v141.5,80 | 8,12.5 IC1.3 | v105,26 134,26 v134,24.5 | QVLIM.2 26.55,11 25.5,11 25.5,16 64,16 64,6 72.5,6 72.5,16 | 72.5,16 72.5,17.5 90,17.5 90,5 136.5,5 v139.5,8 | 61.65,73.95 61.6,74 58,74 v57.5,73.5 R1.2 | 72.5,16 v72,16 | v37,50 38,50 | v20,10.5 C7.2 | v137,66 R9.2
  pour Bottom (isolate 1, rank 3): 26.5,9.5 26.5,12.5 20,12.5 20,9.5 24.5,10.5
A  (via drill 0.6)  (1 unrouted)
  Top 0.5: 85,53.5 v85,56.5
  Bottom 0.5: D1.C 90,87.2 90,86.5 89.5,86 89.5,77 88,75.5 v85,75.5
  pour Top (isolate 2, rank 3): 68,58 89,58 89.5,58.5 89.5,52.5 88,51 71,51 65.5,45.5 60.5,45.5 60.5,51
B1C2  (via drill 0.6 pad 1.5)
  Top 0.5: v119,79 118,80 v118,92
  Bottom 0.406: Q20.C 119.1,93.6 119,93.5 119,90.1 R37.1
  Bottom 0.5: v119,79 R38.1 122.45,80.6 Q21.B | v118,92 118.9,91.1 R37.1
BOOST_EN  (via drill 0.5 pad 1.5, 0.6 pad 1.5)
  Top 0.4: 29.5,47 36.5,54
  Top 0.406: 54.5,76 v66.5,76
  Top 0.5: 54.5,76 36.5,59.5 36.5,54 | 29.5,47 23,47 15,39.5 v15,31
  Bottom 0.406: 67,75.1 R6.2 | v66.5,76 67,75.1 | Q24.C 66.1,73.1 67,74 67,75.1
  Bottom 0.5: D19.C 15,33 v15,31
C
  Top 0.5: R63.1 84,43.9 R64.2
  Top 1.27: R64.2 BATT-.1
  Top 3: BATT-.1 X1.C
C1
  Bottom 0.5: Q21.C 127.6,84.5 U$1.4 129.5,84.75 129.5,86 | 129.5,86 L1.1 | D8.K 133.58,86 129.5,86
CB  (via drill 0.6)
  Top 0.5: v30.5,10.5 30.5,2 144.5,2 v145.5,2.5
  Bottom 0.406: 146,20.5 146,74
  Bottom 0.5: RBZEN1.2 28.6,9.25 QVLIM.1 30,10.95 30,11.5 30.3,11.2 D3.C 31.2,9.7 v30.5,10.5 | 146,20.5 146,3 v145.5,2.5 | 146,74 138,74 137.5,74.5 137,75 300U.2
  Bottom 1: OK2.2 136.73,75.27 137,75
  pour Bottom (isolate 1, rank 3): 28.5,13 33.5,13 33.5,11 33,10.5 30.5,10.5 29,9 28.5,9 28,9.5 28,13
DQ18
  Top 0.5: 40.98,25.25 Q19.3 | Q18.3 21,26 29.5,34.5 35,35 TR1.1
  Top 3: TR1.1 40.98,25.25
  pour Top (isolate 2): 17.5,18.5 28,18.5 29,19.5 29,24 30.5,22.5 48.5,22.5 48.5,26 48.5,35.5 17.5,35.5
EB
  Bottom 0.5: Q21.E 124,84.85 R36.2 126.2,86.9 126.5,87.2 R40.1 127,87.1 127.4,87.2 128.9,88.9 129,89 132,89 132,89.05 RTOP2.2
G  (via drill 0.6)
  Top 0.5: R52.2 44.6,46.8 D9.A | X1.G v91.5,70
  Bottom 0.406: 91.5,71 92,71.5 RTOP1.2
  Bottom 0.5: 110.5,84.5 109.5,82.5 106,80.55 RBZEN.1 RTOP1.2 | 110.5,84.5 115,85.5 | 115,85.5 120.5,85.5 120.75,85.25 | 120.75,85.25 121,86 C8.2 | 120.75,85.25 120.75,87.25 121.5,88 122.9,88 R36.1 124,90.85 Q20.E | OK2.4 139,87.27 139,96 138.5,96.5 118.5,96.5 115,93 115,85.5 | v91.5,70 91.5,71 | D5.C 85.7,79.2 85.5,79 83.5,79 80.5,76 80.5,73.31 C10.1 | 110.5,84.5 R67.1
  pour Top (isolate 2, rank 2): 92.5,66 93,66.5 93,69.5 90,72.5 74.5,72.5 70,68 65.5,68 47,49.5 47,46.5 47.5,46 56.5,46 57,46.5 57,50 75,68 87.5,68 89.5,66 90.5,66
GND1
  Bottom 0.5: TPS1.4 12.8,8.65 C6.1
GQ18  (via drill 0.6)
  Top 0.406: Q18.2 R48.2 36.91,14.41 39.5,15 44.5,15 44.5,18.5 Q19.2
  Top 0.5: 39.5,10.5 39.5,15.31 36.91,14.41 | v31,23 31,14.47 Q18.2 | v55,10 U$2.2 43,10 41.5,11.5
  Bottom 0.5: Q23.1 28.5,31.35 v31,23 | v55,10 57,10
  pour Top (isolate 2, rank 2): 30,24 33.5,24 34,23.5 34,17 42,17 42.5,17.5 42.5,20 48,20 49,19 54.5,10.5 28.5,10.5 26,12.5 23,12.5 23,17
  pour Top (rank 2): 48,12 49,12.5 65,12.5 65,8 48,8
  pour Bottom (rank 2): 48,12 49,12.5 61,12.5 61,8 48,8
N$1
  Bottom 0.5: RBZEN.2 300U.1
N$3
  Bottom 0.5: OK2.3 136.73,90.32 RTOP2.1
N$4
  Bottom 0.406: 46.5,60.5 45.5,61.5
  Bottom 0.5: Q8.1 124.5,48.35 124.5,47 126.5,45 132,40.5 132,34 46.5,34 46.5,60.5 | 45.5,61.5 R58.1
N$5
  Bottom 0.5: 21.5,93.23 OK1.1 | 21.5,93.23 24.5,93.23 C2.+ | R12.S 22,87.5 21,88.5 21,92.73 21.5,93.23
N$6
  Bottom 0.406: 50,69 51.5,69
  Bottom 0.5: R43.1 50,69 | 51.5,69 51.5,55 52.5,54 62.5,54 62.5,54.85 Q3.1
N$7
  Bottom 0.5: Q6.3 132.5,54.75 LED6.C
N$8
  Bottom 0.5: R17.2 18.1,9 18.1,7.7 R18.2
N$10
  Bottom 0.5: Q8.3 123.5,53.75 LED8.C
N$11
  Bottom 0.5: Q2.1 67.45,52.45 67,52 51.5,52 49.5,54 49.5,66.5 R42.1
N$12
  Bottom 0.406: 48,50 48,63
  Bottom 0.5: Q1.1 72.45,50.95 71.5,50 48,50 | 48,63 46.5,64 R41.1
N$14
  Bottom 0.5: Q5.1 137.95,46.55 138,45 138,30 137.5,28 42,28 42,53 R55.1
N$16
  Bottom 0.406: 144,72 144,5 142,3 88.5,3 88.5,16 74,16 74,4 62.5,4 62.5,14 27.5,14 QVLIM.3
  Bottom 0.5: 144,72 115.55,72 5M.1
N$17
  Bottom 0.5: LED7.C 129,51.6 Q7.3
N$18
  Bottom 0.5: R16.1 30,95.5 66,95.5 D15.A
N$19
  Bottom 0.5: LED1.C 70.25,60.75 71.5,59.5 Q1.3
N$20
  Bottom 0.5: LED1.A 71.65,64.25 R3.1
N$21  (via drill 0.6)
  Top 0.5: v106,22.5 106,23.9 R29.1 103,23 102.5,22.5 100.5,22.5 100.1,22.9 Q14.B
  Bottom 0.5: R11.2 129,67.5 129.5,68 140,68 140,22 108.5,22 v106,22.5
N$22
  Bottom 0.5: LED2.C 65.5,59.1 Q2.3
N$23
  Bottom 0.5: D15.C D14.A
N$24
  Bottom 0.5: D14.C D13.A
N$25
  Bottom 0.5: LED2.A R28.1
N$26
  Bottom 0.5: R12.A 19.94,84.96 R13.2
N$27
  Bottom 0.406: R51.1 R33.2
  Bottom 0.5: R46.1 12.4,37.9 13.5,38 D19.A 15.5,37 17.5,35 18.3,35 D18.C 21.4,34.8 R51.1 26.7,34.9 Q23.3 R45.1 27.85,36.1 R32.2
N$28
  Bottom 0.406: 136,30 136,43 133.5,47.5 133.5,48.35 Q6.1
  Bottom 0.5: 136,30 43.5,30 43.5,56.5 R56.1
N$29
  Bottom 0.5: RTOP1.1 5M.2
N$30
  Bottom 0.406: R44.1 53.5,71.5 53.5,57 54,56.5 54.95,56.5 Q4.1
N$31
  Bottom 0.5: Q7.1 129,47.85 131.5,45.5 134,42.5 134,32 45,32 45,58 44,59 R57.1
N$32
  Bottom 0.406: Q3.3 LED3.C
N$33
  Bottom 0.5: LED4.C 57.5,57.6 Q4.3
N$34
  Bottom 0.5: R19.1 63.3,88.8 D7.A
N$35
  Bottom 0.5: D7.C 69.2,82 D6.A
N$36
  Bottom 0.5: LED4.A R1.1
N$37
  Top 0.5: R30.2 Q12.C
N$38
  Bottom 0.5: D6.C D5.A
N$39
  Bottom 0.5: R10.E 59.86,89.54 R19.2
N$40
  Bottom 0.5: R10.A 55.77,84.33 R20.2
N$41
  Bottom 0.5: R4.1 41.6,93 64.5,93 70,87.5 D4.A
N$42
  Bottom 0.5: D4.C D2.A
N$43
  Bottom 0.5: D2.C D1.A
N$44
  Bottom 0.5: R2.E 37.27,89.77 37.5,90 R4.2
N$45
  Bottom 0.5: R2.A 37.27,82.87 R5.2
N$47
  Bottom 0.5: LED5.A R9.1
N$48
  Bottom 0.5: 51.5,87.1 R22.1 | C5.+ 51.5,87.1 | R10.S 55.67,87.1 51.5,87.1
N$49
  Top 0.5: Q14.C 97.9,24.9 97,24 97,23 96,22 89,22 88,23 R35.2
N$50
  Top 0.5: R31.2 64.5,18.4 | 64.5,18.4 R30.1 | R23.2 64.4,19.5 64.5,18.4
N$51
  Top 0.5: Q16.B 112.54,29.96 114,28.5 | 114,28.5 115.69,28.5 Q10.1 116.9,27.29 R24.2 | R34.1 113,27.5 114,28.5
N$52
  Bottom 0.5: Q5.3 LED5.C
N$53  (via drill 0.6)  (1 unrouted)
  Top 0.5: R25.1 72.9,19.75 Q12.B 72.55,20.05 v71,18.5 | v133,66 133,64
  Bottom 0.5: R7.2 v133,66 | v71,18.5 71.5,19
N$54
  Top 0.5: R31.1 62.5,23 63.75,23 Q9.1
N$55  (via drill 0.6)
  Top 0.5: v132,19 129.5,19 128.6,19.9 R27.1 127.6,23 126,23 125.6,23.4 Q13.B
  Bottom 0.5: R21.2 122.9,65.9 126.5,69.5 141.5,69.5 142,69 142,19 v132,19
N$56  (via drill 0.6)
  Top 0.5: 14.5,25.5 v15,27 15,14.5 15.5,14.5 15.5,14.47 Q18.1
  Bottom 0.5: v15,27 R33.1
N$57
  Top 0.5: R34.2 113,23.5 113.5,23 123,23 123.5,23.5 123.5,25.4 Q13.C
N$58  (via drill 0.6)
  Top 0.5: v34,23 34,19.5 35.5,19.5 37.03,17.97 Q19.1
  Bottom 0.5: R32.1 32.5,32.4 v34,23
N$59
  Top 0.406: Q17.B 88.54,29.96 89.5,28.5 90.69,28.5 Q11.1 91.72,26.18 R26.2
  Top 0.5: R35.1 88,27 89.5,28.5
N$60
  Bottom 0.5: R37.2 121.1,91.85 U$1.1
N$61
  Bottom 0.5: C8.1 121,82.25 U$1.2
N$62
  Bottom 0.5: R38.2 R39.2
N$63
  Bottom 0.5: R40.2 126.45,89.65 Q20.B
N$64
  Bottom 0.5: 11.25,40.75 TR1.7 | 10.5,40.5 10,40.4 R46.2
  Bottom 1: 10.5,40.5 11.25,40.75
N$65
  Bottom 0.5: R12.E 26.54,90.04 28,91.5 28,92.4 R16.2
N$66
  Top 0.5: 358.2 95.9,12.4 96,12.5 100,12.5 | 100,12.5 100.1,12.4 Q25.2 | R63.2 84,23 90.5,18 100,18 100,12.5
N$67
  Top 0.5: 358.1 95.1,9.95 Q26.2 97.5,9 | 97.5,9 97.65,9 Q25.3 | Q25.1 100.1,9.1 100,9 97.5,9
N$71
  Bottom 0.5: Q22.3 20.5,39.6 R51.2
N$74
  Bottom 0.5: C9.1 10.85,32.1 TR1.9
N$75  (via drill 0.6)
  Top 0.5: v110.5,97 144.5,97 145.5,96 145.5,7.5 140.5,4.5 99.15,4.5 Q26.1 95.6,6.6 94.5,5.5 93,5.5 | D20.A 81.3,4.5 92.5,4.5 93,5.5 | 93,5.5 93,7.6 Q26.3
  Bottom 0.5: v110.5,97 R59.1
N$80  (via drill 0.6 pad 1.5)
  Top 0.5: R52.1 35,46.5 v27.5,41.25
  Bottom 0.5: R45.2 v27.5,41.25
N$81
  Bottom 0.406: R53.2 R54.1 63.75,71.9 Q24.B 63.95,72
N$82
  Bottom 0.406: LED3.A R53.1
N$85
  Top 0.5: R65.E 78.23,8.47 D20.C
N$86
  Top 0.5: R65.S 80.4,12.7 80.4,14.5 81.5,15.5 88.31,15.5 358.5
N$87
  Top 0.5: R66.2 86.1,13.9 86,13.6 87.56,13.6 358.6 88.44,13.7 90.1,13.7 90.6,13.1 R61.1 90.6,8.1 90.5,8 90,6.5 84.3,6.5 83.8,7.8 R62.1
N$88
  Bottom 0.5: R67.2 R59.2
N$89
  Top 0.5: R62.2 84.45,11.55 83,13 R60.2 | R62.2 85.55,11.55 86,11.5 86.86,12.4 358.7 | U$2.1 47.09,14 70,14 75.5,10.5 75.5,6.5 81.5,6.5 81.5,10.5 83.05,11.55 R62.2
N$90
  Top 0.5: R68.2 78,16.37 R65.A
NODOTL2
  pour Top (isolate 2, rank 2): 33.5,43 66,43 66.5,42.5 66.5,38.5 33.5,39
PRB1  (via drill 0.6)
  Top 0.5: v17,45.5 17,48 20,50.5 30,50.5 34.5,55 34.5,61.5 44.5,72 44.5,86 43,87.5 37.77,87.5 R2.S
  Bottom 0.5: R8.1 R2.S 40.27,87 C4.+ | Q22.1 18.9,43.6 v17,45.5
RB0  (via drill 0.6 pad 1.5)
  Top 0.406: v47,85.5 47,93 33.5,93 33.5,80 6.5,80 6.5,65 7.5,63.5 JP3.4
  Bottom 0.406: v47,85.5 R22.2
  Bottom 0.5: JP3.4 9.54,63.46 10.54,63.46 13,61 14.5,61 14.96,61.46 MIC.13
RB1  (via drill 0.6 pad 1.5)
  Top 0.406: v31,85 31,82 5.5,82 5.5,61 8.96,61 JP3.5
  Bottom 0.406: R8.2 31,87 v31,85
  Bottom 0.5: JP3.5 9.54,61 10,61 9.97,60.97 9.97,60.92 12.5,59.5 16,59.5 16.2,59.81 16.23,59.84 MIC.12
RB2  (via drill 0.6 pad 1.5)
  Top 0.406: v12,91 4,84 4,58.5 9.42,58.5 JP3.6
  Bottom 0.406: R14.2 8.5,91 v12,91
  Bottom 0.5: MIC.11 17.5,57.8 10.88,57.8 | 10.88,57.8 9.19,58.3 | JP3.6 10.88,57.8 | OK1.4 9.69,92.21 R14.2
RB4
  Bottom 0.5: MIC.3 16.23,66.77 17,66 24,66 25.5,63.5 JP6.4 28.5,63.5 29,64
RB5
  Bottom 0.5: MIC.2 14.96,66.04 16,65 23,65 23,61 JP6.3 27.54,61.5 R58.2
RC0
  Bottom 0.5: MIC.10 18.77,56 11.5,56 8.73,55.8 9.42,55.8 JP3.7 R55.2
RC1
  Bottom 0.5: MIC.9 20.04,56.96 21,55.8 26.88,55.8 JP6.1 27.5,55.88 | 27.5,55.88 27.83,55.88 28.45,56.5 R56.2 | 27.5,55.88 27.62,56
RC2
  Bottom 0.5: MIC.8 21.31,59.49 22.1,58.5 25.08,58.5 JP6.2 27.58,59 R57.2
RC3
  Bottom 0.5: MIC.7 24.14,67.86 25.5,66.5 26,66.5 26.5,66 26.96,66 JP6.5 27.46,66.5 R42.2
RC4
  Bottom 0.5: MIC.6 20,67.9 20,70 24,70 25.42,68.58 JP6.6 27.42,69 R43.2
RC5
  Bottom 0.5: MIC.5 18.77,69.46 18.8,69.49 18.8,70.9 19.12,71.12 JP6.7 27.38,71.5 R44.2
S  (via drill 0.6)
  Top 0.5: v101.5,98 101.5,65.5 X1.S
  Bottom 0.5: 22.5,98 22,96.5 21,95.5 20.58,95.5 OK1.2 20.08,96 19.5,96 18.5,95 R13.1 | 22.5,98 v101.5,98 | C2.- 23.23,96.27 22.5,98
T  (via drill 0.6)
  Top 0.5: v95,93 95,74 X1.T
  Bottom 0.5: D13.C 94.5,93.5 v95,93
U
  Top 0.5: 102.38,56.12 X1.U | Q17.C 94,40.96
  Top 3: 102.38,56.12 105,54.5 105,51.5 99.5,46 94,46 94,40.96 | Q11.3 Q17.C
V5  (via drill 0.6)  (1 unrouted)
  Top 0.5: v11.5,68.5 11,68.5
  Bottom 0.5: MIC.1 12.97,68.58 JP3.2 9.58,68.5 v11.5,68.5 | R14.1 6.4,92.1 5.5,93 3,93 2.5,92.5 v2.5,68.5 2.5,47.95 C12.1 2.95,45.05 3,45 3,44.27 IC2.1
V+  (via drill 0.6)
  Top 0.5: R61.2 358.8 88.09,10.6 v86.5,9.5
  Bottom 0.5: 3,16.5 3,11.5 IC1.1 5.5,11.73 3.5,10 3.5,2.5 13.5,2.5 | 3,16.5 3,39 IC2.3 4,40.5 | 3,16.5 C1.1 | v86.5,9.5 86,9 86,3 85.5,2 15.5,2 | 13.5,2.5 15.5,2 | TPS1.5 12.8,2.7 13.5,2.5 | R15.2 15.6,2.6 15.5,2
V-  (via drill 0.6, 0.8)
  Top 0.406: 358.3 358.4
  Top 0.5: R48.1 36.27,8.1 | Q17.E 99.46,31.46 96,28.5 95.81,28.5 Q11.2 94.1,25.79 R26.1 | 358.4 95.91,14.9 v96,15 | R64.1 v80,48 | v133.5,79 130.5,79 v119,67.5 | R23.1 67.6,22.29 Q9.2 | R68.1 78,20 | R60.1 83.1,18.4 83,18.5 | R66.1 85.5,18.5 | U$2.3 45.9,5.9 45.5,5.5
  Bottom 0.5: 10.55,10.55 10.5,10.5 10.5,10.15 TPS1.3 TPS1.2 | 10.55,10.55 C6.2 | 10.55,10.55 11,11 14.9,11 R17.1 15.6,9.3 R15.1 17.8,5.6 R18.1 21.1,5.4 21.5,5 | MIC.14 13.69,63.31 11,66 7,66 | 9.54,66 JP3.3 | OK1.3 12.92,96 15,96 15,82.5 | IC1.2 6.5,15 7,15.5 7,16.45 C1.2 | v43,5.5 44.5,5.5 | Q23.2 26.05,27.05 26,27 | Q22.2 23.9,43.6 24,43.5 | v96,15 96,20 | IC2.2 7.5,42 8,42.5 8,43.5 | v133.5,79 R39.1 | 119,62.5 v119,67.5
  Bottom 1.5: 11,66 9.54,66
  other vias: 52.9,23.8 71,38 69.5,9
  pour Bottom (isolate 1.9, rank 4): 1.5,85 65.5,85.5 83.5,70.5 87.5,70.5 90,65 109.5,65 112,71 114,71 114,94 147.5,93 147,1.5 3.5,2.5
  pour Bottom (isolate 0.61, rank 4): 121.5,59 138,59 138,59.5 139,58.5 139,46 138.5,45.5 121,45.5
  pour Bottom (isolate 0.61, rank 4): 55.5,68.5 72,68.5 72,69 73,68 70,65 70,58.5 73,55.5 72.5,54 55,55
  pour Top (isolate 1.9, rank 4): 1.5,85 52,85.5 52,42.5 67.5,42 70,68 86.5,68.5 89,68 89,48.5 98.5,43 117.5,43 114,57.5 114,81 147.5,81 147,1.5 1.5,1.5
WIND
  Bottom 0.5: MIC.4 17.5,70.5 17.42,71.08 9,71.08 | 9,71.08 8.57,71.08 | 9.5,71 JP3.1 9.04,71.12 9,71.08
Y
  Top 0.5: 118,40.96 Q16.C Q10.3
  Top 3: X1.Y 107,62 118,51 118,40.96

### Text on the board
Top: MICHAEL5.net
